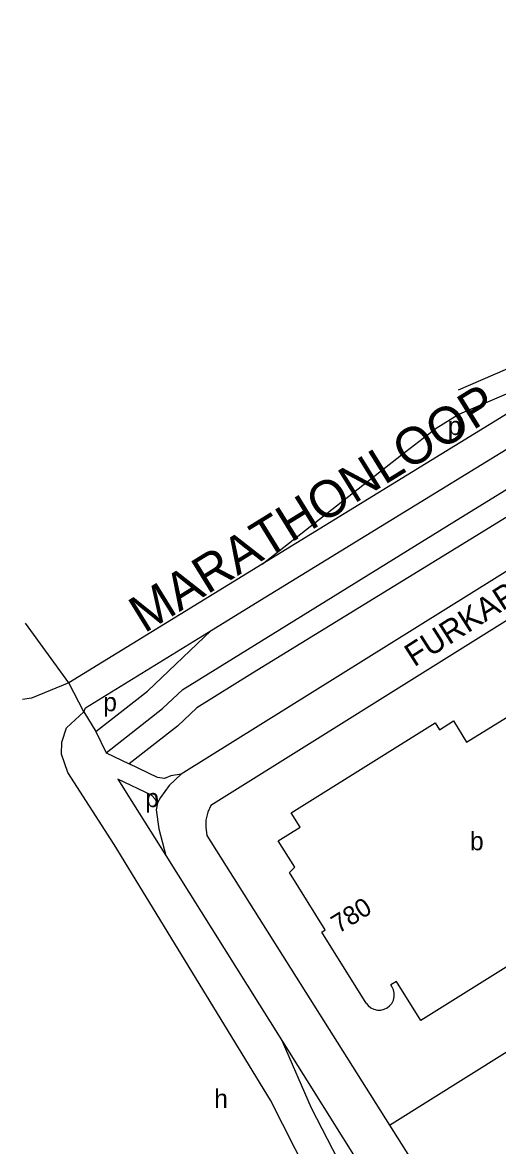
# Model space of a CAD drawing. Extents: x 158848 to 160613, y 385889 to 387762.
# Drawn here: x 158847.9 to 158951, y 387116.4 to 387360.1 of the extents above; entities that cross this region are included whole.
import ezdxf

# ---------------------------------------------------------------- set-up
doc = ezdxf.new("R2010")
doc.units = 0
for name, color, linetype in [('BLT_Basislijn', 7, 'Continuous'), ('BLT_Bebouwing', 7, 'Continuous'), ('BLT_Centroide', 7, 'Continuous'), ('BLT_Huisnummer', 7, 'Continuous'), ('BLT_Straatnaam', 7, 'Continuous'), ('BLT_Straatnaam_hoofdweg', 7, 'Continuous'), ('BLT_Vlakafsluiter', 7, 'Continuous')]:
    doc.layers.add(name, color=color, linetype=linetype)

msp = doc.modelspace()

# ---------------------------------------------------------------- linework, layer by layer
at = {"layer": 'BLT_Basislijn'}
for p, q in [((159018.8, 387293.41), (158948.38, 387250)), ((158961.17, 387280.21), (158899.9, 387242.56)), ((158967.29, 387250), (158882.37, 387196.98)), ((158948.38, 387250), (158897.83, 387218.91)), ((158899.9, 387242.56), (158857.99, 387216.81)), ((158861.21, 387210.57), (158863.84, 387206.28)), ((158866.04, 387201.65), (158871.09, 387199.25)), ((158872.02, 387190.51), (158878.99, 387179.39)), ((158878.99, 387179.39), (158904.33, 387138.99)), ((158904.33, 387138.99), (159120.99, 386793.5)), ((158927.58, 387120.88), (158953.1, 387136.81))]:
    msp.add_line(p, q, dxfattribs=at)
for points in [[(158888.87, 387228.17), (158897.56, 387233.51), (158936.43, 387257.38), (158966.21, 387275.66), (158998.48, 387295.52), (159028.3, 387313.75), (159057.18, 387331.51), (159061.69, 387334.26), (159063.8, 387335.23), (159073.81, 387338.52), (159076.27, 387339.74), (159110.17, 387360.14)], [(158866.04, 387201.65), (158878.3, 387211.25), (158882.68, 387215.41), (158895.2, 387223.16), (158941.52, 387251.8), (159042.66, 387314.04), (159107.41, 387353.95)], [(158942.51, 387280.45), (158955.4, 387286.01), (158973.67, 387294.39)], [(158980.27, 387291.91), (158957.43, 387281.44), (158942.27, 387274.9)], [(158899.9, 387242.56), (158930.18, 387266.34), (158937.69, 387272.08), (158942.27, 387274.9)], [(158953.84, 387230.87), (158888.76, 387190.2), (158888.1, 387188.78), (158887.67, 387187.07), (158887.68, 387185.51), (158887.94, 387183.69), (158927.58, 387120.88)], [(158861.21, 387210.57), (158861.6, 387211.41), (158888.87, 387228.17)], [(158863.84, 387206.28), (158875.03, 387215.04), (158888.87, 387228.17)], [(158897.83, 387218.91), (158885.75, 387211.43), (158881.57, 387207.46), (158871.09, 387199.25)], [(158857.99, 387216.81), (158849.85, 387213.49), (158847.91, 387213.19)], [(158981.27, 386995.93), (158970.33, 387013.12), (158959.33, 387027), (158918.71, 387092.14), (158915.02, 387100), (158901.75, 387126.26), (158867.81, 387181.73), (158857.76, 387197.35), (158856.39, 387201.34), (158856.42, 387203.96), (158857.49, 387207.05), (158861.21, 387210.57)], [(158882.37, 387196.98), (158880.11, 387196.69), (158878.73, 387196.04), (158877.23, 387196.3), (158871.09, 387199.25)], [(158877.21, 387190.79), (158876.74, 387191.51), (158875.88, 387192.44), (158868.63, 387195.92), (158872.02, 387190.51)], [(158882.37, 387196.98), (158879.74, 387194.58), (158877.83, 387191.97), (158877.21, 387190.79)], [(158877.21, 387190.79), (158876.93, 387189.25), (158877.51, 387185.18), (158878.99, 387179.39)], [(158996.31, 386982.75), (158923.31, 387100), (158910.6, 387124.57), (158904.33, 387138.99)], [(158927.58, 387120.88), (158974.53, 387046.48)]]:
    msp.add_lwpolyline(points, dxfattribs=at)
at = {"layer": 'BLT_Bebouwing'}
for points in [[(158944.27, 387203.93), (158961.06, 387214.27), (158959.99, 387215.98), (158962.28, 387217.42)], [(158906.22, 387188.62), (158937.45, 387208.13), (158938.38, 387206.67), (158941.42, 387208.56), (158944.27, 387203.93)], [(158922.49, 387147.35), (158912.86, 387162.76), (158913.58, 387163.21), (158905.82, 387175.68), (158907.01, 387176.83), (158903.41, 387182.58), (158908.14, 387185.54), (158906.22, 387188.62)], [(158987.62, 387176.81), (158934.33, 387143.57), (158929.07, 387152.04), (158927.84, 387151.28)], [(158922.49, 387147.35), (158922.92, 387146.81), (158923.49, 387146.34), (158924.17, 387146), (158924.93, 387145.83), (158925.69, 387145.83), (158926.41, 387146), (158927.03, 387146.3), (158927.58, 387146.72), (158928.05, 387147.28), (158928.39, 387147.97), (158928.58, 387148.72), (158928.58, 387149.48), (158928.42, 387150.2), (158928.12, 387150.83), (158927.84, 387151.28)]]:
    msp.add_lwpolyline(points, dxfattribs=at)
at = {"layer": 'BLT_Vlakafsluiter'}
for p, q in [((158857.99, 387216.81), (158848.55, 387229.8)), ((158861.21, 387210.57), (158857.99, 387216.81)), ((158863.84, 387206.28), (158866.04, 387201.65))]:
    msp.add_line(p, q, dxfattribs=at)

# ---------------------------------------------------------------- texts
at = {"layer": 'BLT_Centroide'}
for s, p in [('p', (158940.21, 387270.61)), ('p', (158865.44, 387210.67)), ('p', (158874.55, 387189.86)), ('b', (158945.02, 387180.5)), ('h', (158889.52, 387124.6))]:
    msp.add_text(s, height=4, dxfattribs=at).set_placement(p)
at = {"layer": 'BLT_Huisnummer'}
msp.add_text('780', height=4, rotation=31.9848, dxfattribs=at).set_placement((158916.5, 387162.36))
at = {"layer": 'BLT_Straatnaam'}
msp.add_text('FURKAPAS', height=5, rotation=32.4906, dxfattribs=at).set_placement((158932.91, 387220.17))
at = {"layer": 'BLT_Straatnaam_hoofdweg'}
msp.add_text('MARATHONLOOP', height=8, rotation=31.7141, dxfattribs=at).set_placement((158874.35, 387227.5))

doc.saveas('drawing.dxf')
